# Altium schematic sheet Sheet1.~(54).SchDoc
size A4; SheetNumber: 1; SheetTotal: 1
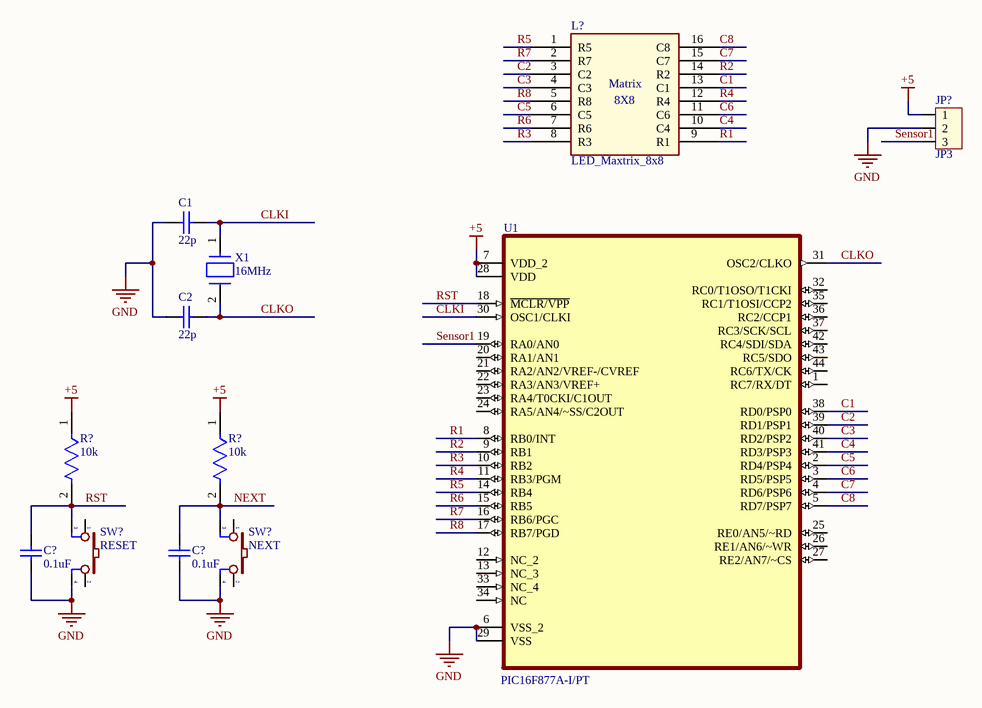
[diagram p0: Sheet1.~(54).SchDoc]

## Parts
(Parts that share a designator on the sheet are numbered #1, #2 ... from top to bottom, then left to right.)
C1  22p  [CAPC2013X94X50LL25T25]
C2  22p  [CAPC2013X94X50LL25T25]
C?#1  0.1uF  [CAPC2013X94X50LL25T25]
C?#2  0.1uF  [CAPC2013X94X50LL25T25]
JP?  JP3  [CON3]
L?  LED_Maxtrix_8x8  [LED_Matrix_8x8]
R?#1  10k  [FP-CR0805-MFG]
R?#2  10k  [FP-CR0805-MFG]
SW?#1  RESET  [SW4]
SW?#2  NEXT  [SW4]
U1  PIC16F877A-I/PT  [TQFP-44]
X1  16MHz  [FP-ABM7-MFG]

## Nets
+5: JP?.1 R?#1.1 R?#2.1 U1.7(VDD_2) U1.28(VDD)
GND: C1.1 C2.1 C?#1.1 C?#2.1 JP?.2 SW?#1.4 SW?#2.4 U1.6(VSS_2) U1.29(VSS)
C1: L?.13(C1) U1.38(RD0/PSP0)
C2: L?.3(C2) U1.39(RD1/PSP1)
C3: L?.4(C3) U1.40(RD2/PSP2)
C4: L?.10(C4) U1.41(RD3/PSP3)
C5: L?.6(C5) U1.2(RD4/PSP4)
C6: L?.11(C6) U1.3(RD5/PSP5)
C7: L?.15(C7) U1.4(RD6/PSP6)
C8: L?.16(C8) U1.5(RD7/PSP7)
CLKI: C1.2 U1.30(OSC1/CLKI) X1.1
CLKO: C2.2 U1.31(OSC2/CLKO) X1.2
NEXT: C?#2.2 R?#2.2 SW?#2.3
R1: L?.9(R1) U1.8(RB0/INT)
R2: L?.14(R2) U1.9(RB1)
R3: L?.8(R3) U1.10(RB2)
R4: L?.12(R4) U1.11(RB3/PGM)
R5: L?.1(R5) U1.14(RB4)
R6: L?.7(R6) U1.15(RB5)
R7: L?.2(R7) U1.16(RB6/PGC)
R8: L?.5(R8) U1.17(RB7/PGD)
RST: C?#1.2 R?#1.2 SW?#1.3 U1.18(~{MCLR/VPP})
Sensor1: JP?.3 U1.19(RA0/AN0)

Not connected (* = marked no-connect by the designer): SW?#1 1 2; SW?#2 1 2; U1 1(RC7/RX/DT) 12(NC_2) 13(NC_3) 20(RA1/AN1) 21(RA2/AN2/VREF-/CVREF) 22(RA3/AN3/VREF+) 23(RA4/T0CKI/C1OUT) 24(RA5/AN4/~SS/C2OUT) 25(RE0/AN5/~RD) 26(RE1/AN6/~WR) 27(RE2/AN7/~CS) 32(RC0/T1OSO/T1CKI) 33(NC_4) 34(NC) 35(RC1/T1OSI/CCP2) 36(RC2/CCP1) 37(RC3/SCK/SCL) 42(RC4/SDI/SDA) 43(RC5/SDO) 44(RC6/TX/CK)

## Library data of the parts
C1 C2 C?#1 C?#2 = LD051C104KAB2A: Cap Ceramic 0.1uF 100V X7R 10% SMD 0805 125°C Embossed T/R; Manufacturer: Kyocera AVX; Value: 100nF
JP? = Con3: Connector 3
R?#1 R?#2 = CR0805-JW-331ELF: Res Thick Film 0805 330 Ohm 5% 1/8W ±200ppm/°C Molded SMD SMD Paper Tape on Plastic Reel; Manufacturer: Bourns; Value: 330R; Power Rating: 125mW; Voltage Rating: 150V
SW?#1 SW?#2 = SW4-1: Switch button 4 pin; Value: SW chip 4 pin
U1 = PIC16F877A-I/PT: PIC16F877A Microcontroller IC 8-Bit 20MHz 14KB _8K x 14_ FLASH 44-TQFP _10x10_; MF: Microchip
X1 = ABM7-16.000MHZ-4-T: Crystal 16MHz ±30ppm (Tol) ±50ppm (Stability) 18pF FUND 50Ohm 2-Pin Mini-CSMD T/R; Manufacturer: Abracon; ESR (Equivalent Series Resistance): 50R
